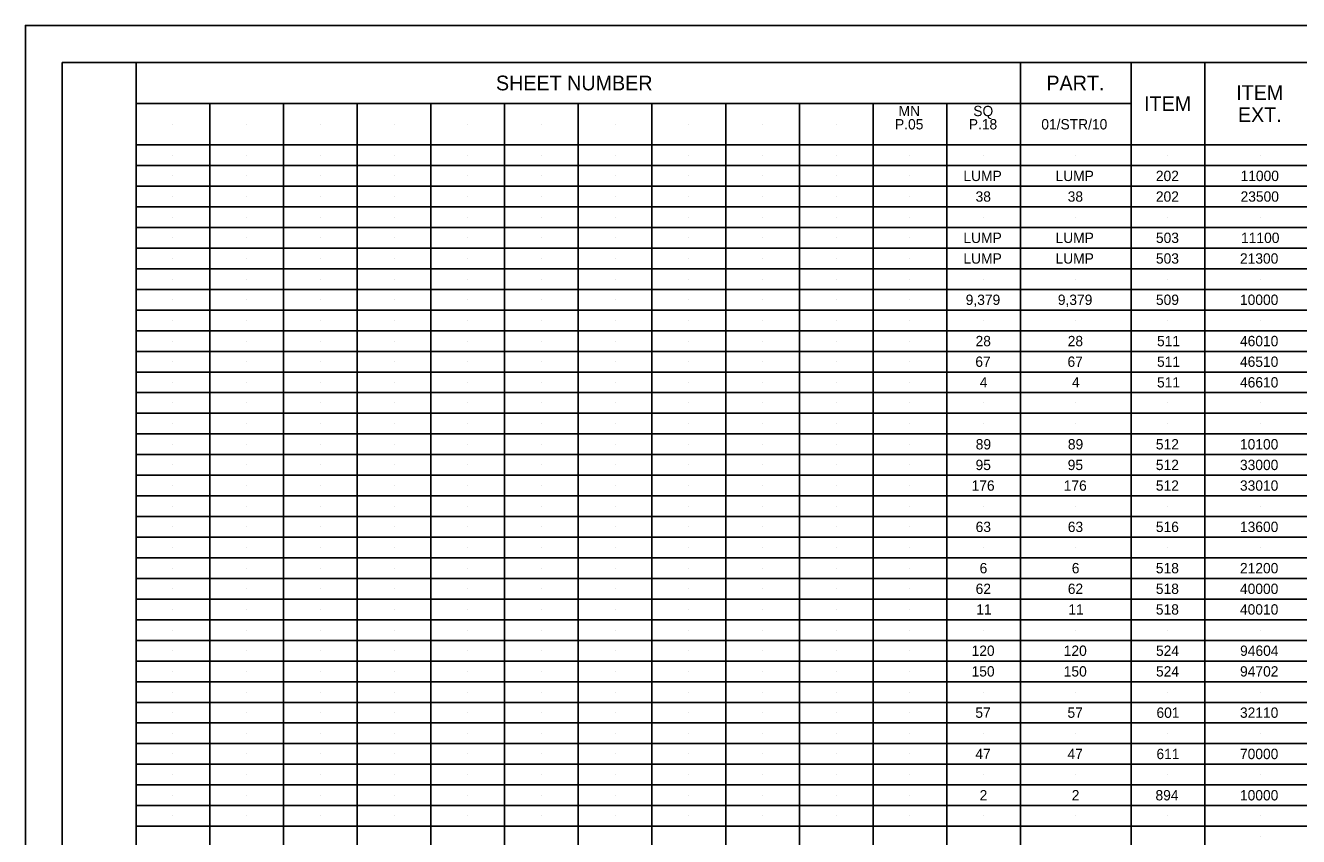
# Model space of a CAD drawing. Extents: x 0 to 34, y 0 to 22.
# Drawn here: x 0 to 17.27, y 11 to 22 of the extents above; entities that cross this region are included whole.
import ezdxf

# ---------------------------------------------------------------- set-up
doc = ezdxf.new("R2010")
doc.units = 0
for name, color, linetype in [('RD_P_Text', 7, 'Continuous'), ('SC_Scratch1', 7, 'Continuous'), ('SC_Scratch2', 7, 'Continuous'), ('SH_Border', 7, 'Continuous'), ('SH_Cut_Line', 7, 'Continuous'), ('SH_Data', 7, 'Continuous')]:
    doc.layers.add(name, color=color, linetype=linetype)

msp = doc.modelspace()

# ---------------------------------------------------------------- linework, layer by layer
at = {"layer": 'SC_Scratch1'}
for p, q in [((2, 20.66), (2, 20.66)), ((3, 20.66), (3, 20.66)), ((4, 20.66), (4, 20.66)), ((5, 20.66), (5, 20.66)), ((6, 20.66), (6, 20.66)), ((7, 20.66), (7, 20.66)), ((8, 20.66), (8, 20.66)), ((9, 20.66), (9, 20.66)), ((10, 20.66), (10, 20.66)), ((11, 20.66), (11, 20.66)), ((12, 20.66), (12, 20.66)), ((13, 20.66), (13, 20.66)), ((14.25, 20.66), (14.25, 20.66)), ((2, 20.24), (2, 20.24)), ((3, 20.24), (3, 20.24)), ((4, 20.24), (4, 20.24)), ((5, 20.24), (5, 20.24)), ((6, 20.24), (6, 20.24)), ((7, 20.24), (7, 20.24)), ((8, 20.24), (8, 20.24)), ((9, 20.24), (9, 20.24)), ((10, 20.24), (10, 20.24)), ((11, 20.24), (11, 20.24)), ((12, 20.24), (12, 20.24)), ((13, 20.24), (13, 20.24)), ((14.25, 20.24), (14.25, 20.24)), ((15.5, 20.24), (15.5, 20.24)), ((16.75, 20.24), (16.75, 20.24)), ((2, 19.96), (2, 19.96)), ((3, 19.96), (3, 19.96)), ((4, 19.96), (4, 19.96)), ((5, 19.96), (5, 19.96)), ((6, 19.96), (6, 19.96)), ((7, 19.96), (7, 19.96)), ((8, 19.96), (8, 19.96)), ((9, 19.96), (9, 19.96)), ((10, 19.96), (10, 19.96)), ((11, 19.96), (11, 19.96)), ((12, 19.96), (12, 19.96)), ((13, 19.96), (13, 19.96)), ((14.25, 19.96), (14.25, 19.96)), ((15.5, 19.96), (15.5, 19.96)), ((16.75, 19.96), (16.75, 19.96)), ((2, 19.68), (2, 19.68)), ((3, 19.68), (3, 19.68)), ((4, 19.68), (4, 19.68)), ((5, 19.68), (5, 19.68)), ((6, 19.68), (6, 19.68)), ((7, 19.68), (7, 19.68)), ((8, 19.68), (8, 19.68)), ((9, 19.68), (9, 19.68)), ((10, 19.68), (10, 19.68)), ((11, 19.68), (11, 19.68)), ((12, 19.68), (12, 19.68)), ((13, 19.68), (13, 19.68)), ((14.25, 19.68), (14.25, 19.68)), ((15.5, 19.68), (15.5, 19.68)), ((16.75, 19.68), (16.75, 19.68)), ((2, 19.4), (2, 19.4)), ((3, 19.4), (3, 19.4)), ((4, 19.4), (4, 19.4)), ((5, 19.4), (5, 19.4)), ((6, 19.4), (6, 19.4)), ((7, 19.4), (7, 19.4)), ((8, 19.4), (8, 19.4)), ((9, 19.4), (9, 19.4)), ((10, 19.4), (10, 19.4)), ((11, 19.4), (11, 19.4)), ((12, 19.4), (12, 19.4)), ((13, 19.4), (13, 19.4)), ((14.25, 19.4), (14.25, 19.4)), ((15.5, 19.4), (15.5, 19.4)), ((16.75, 19.4), (16.75, 19.4)), ((2, 19.12), (2, 19.12)), ((3, 19.12), (3, 19.12)), ((4, 19.12), (4, 19.12)), ((5, 19.12), (5, 19.12)), ((6, 19.12), (6, 19.12)), ((7, 19.12), (7, 19.12)), ((8, 19.12), (8, 19.12)), ((9, 19.12), (9, 19.12)), ((10, 19.12), (10, 19.12)), ((11, 19.12), (11, 19.12)), ((12, 19.12), (12, 19.12)), ((13, 19.12), (13, 19.12)), ((14.25, 19.12), (14.25, 19.12)), ((15.5, 19.12), (15.5, 19.12)), ((16.75, 19.12), (16.75, 19.12)), ((2, 18.84), (2, 18.84)), ((3, 18.84), (3, 18.84)), ((4, 18.84), (4, 18.84)), ((5, 18.84), (5, 18.84)), ((6, 18.84), (6, 18.84)), ((7, 18.84), (7, 18.84)), ((8, 18.84), (8, 18.84)), ((9, 18.84), (9, 18.84)), ((10, 18.84), (10, 18.84)), ((11, 18.84), (11, 18.84)), ((12, 18.84), (12, 18.84)), ((13, 18.84), (13, 18.84)), ((14.25, 18.84), (14.25, 18.84)), ((15.5, 18.84), (15.5, 18.84)), ((16.75, 18.84), (16.75, 18.84)), ((2, 18.56), (2, 18.56)), ((3, 18.56), (3, 18.56)), ((4, 18.56), (4, 18.56)), ((5, 18.56), (5, 18.56)), ((6, 18.56), (6, 18.56)), ((7, 18.56), (7, 18.56)), ((8, 18.56), (8, 18.56)), ((9, 18.56), (9, 18.56)), ((10, 18.56), (10, 18.56)), ((11, 18.56), (11, 18.56)), ((12, 18.56), (12, 18.56)), ((13, 18.56), (13, 18.56)), ((14.25, 18.56), (14.25, 18.56)), ((15.5, 18.56), (15.5, 18.56)), ((16.75, 18.56), (16.75, 18.56)), ((2, 18.28), (2, 18.28)), ((3, 18.28), (3, 18.28)), ((4, 18.28), (4, 18.28)), ((5, 18.28), (5, 18.28)), ((6, 18.28), (6, 18.28)), ((7, 18.28), (7, 18.28)), ((8, 18.28), (8, 18.28)), ((9, 18.28), (9, 18.28)), ((10, 18.28), (10, 18.28)), ((11, 18.28), (11, 18.28)), ((12, 18.28), (12, 18.28)), ((13, 18.28), (13, 18.28)), ((14.25, 18.28), (14.25, 18.28)), ((15.5, 18.28), (15.5, 18.28)), ((16.75, 18.28), (16.75, 18.28)), ((2, 18), (2, 18)), ((3, 18), (3, 18)), ((4, 18), (4, 18)), ((5, 18), (5, 18)), ((6, 18), (6, 18)), ((7, 18), (7, 18)), ((8, 18), (8, 18)), ((9, 18), (9, 18)), ((10, 18), (10, 18)), ((11, 18), (11, 18)), ((12, 18), (12, 18)), ((13, 18), (13, 18)), ((14.25, 18), (14.25, 18)), ((15.5, 18), (15.5, 18)), ((16.75, 18), (16.75, 18)), ((2, 17.72), (2, 17.72)), ((3, 17.72), (3, 17.72)), ((4, 17.72), (4, 17.72)), ((5, 17.72), (5, 17.72)), ((6, 17.72), (6, 17.72)), ((7, 17.72), (7, 17.72)), ((8, 17.72), (8, 17.72)), ((9, 17.72), (9, 17.72)), ((10, 17.72), (10, 17.72)), ((11, 17.72), (11, 17.72)), ((12, 17.72), (12, 17.72)), ((13, 17.72), (13, 17.72)), ((14.25, 17.72), (14.25, 17.72)), ((15.5, 17.72), (15.5, 17.72)), ((16.75, 17.72), (16.75, 17.72)), ((2, 17.44), (2, 17.44)), ((3, 17.44), (3, 17.44)), ((4, 17.44), (4, 17.44)), ((5, 17.44), (5, 17.44)), ((6, 17.44), (6, 17.44)), ((7, 17.44), (7, 17.44)), ((8, 17.44), (8, 17.44)), ((9, 17.44), (9, 17.44)), ((10, 17.44), (10, 17.44)), ((11, 17.44), (11, 17.44)), ((12, 17.44), (12, 17.44)), ((13, 17.44), (13, 17.44)), ((14.25, 17.44), (14.25, 17.44)), ((15.5, 17.44), (15.5, 17.44)), ((16.75, 17.44), (16.75, 17.44)), ((2, 17.16), (2, 17.16)), ((3, 17.16), (3, 17.16)), ((4, 17.16), (4, 17.16)), ((5, 17.16), (5, 17.16)), ((6, 17.16), (6, 17.16)), ((7, 17.16), (7, 17.16)), ((8, 17.16), (8, 17.16)), ((9, 17.16), (9, 17.16)), ((10, 17.16), (10, 17.16)), ((11, 17.16), (11, 17.16)), ((12, 17.16), (12, 17.16)), ((13, 17.16), (13, 17.16)), ((14.25, 17.16), (14.25, 17.16)), ((15.5, 17.16), (15.5, 17.16)), ((16.75, 17.16), (16.75, 17.16)), ((2, 16.88), (2, 16.88)), ((3, 16.88), (3, 16.88)), ((4, 16.88), (4, 16.88)), ((5, 16.88), (5, 16.88)), ((6, 16.88), (6, 16.88)), ((7, 16.88), (7, 16.88)), ((8, 16.88), (8, 16.88)), ((9, 16.88), (9, 16.88)), ((10, 16.88), (10, 16.88)), ((11, 16.88), (11, 16.88)), ((12, 16.88), (12, 16.88)), ((13, 16.88), (13, 16.88)), ((14.25, 16.88), (14.25, 16.88)), ((15.5, 16.88), (15.5, 16.88)), ((16.75, 16.88), (16.75, 16.88)), ((2, 16.6), (2, 16.6)), ((3, 16.6), (3, 16.6)), ((4, 16.6), (4, 16.6)), ((5, 16.6), (5, 16.6)), ((6, 16.6), (6, 16.6)), ((7, 16.6), (7, 16.6)), ((8, 16.6), (8, 16.6)), ((9, 16.6), (9, 16.6)), ((10, 16.6), (10, 16.6)), ((11, 16.6), (11, 16.6)), ((12, 16.6), (12, 16.6)), ((13, 16.6), (13, 16.6)), ((14.25, 16.6), (14.25, 16.6)), ((15.5, 16.6), (15.5, 16.6)), ((16.75, 16.6), (16.75, 16.6)), ((2, 16.32), (2, 16.32)), ((3, 16.32), (3, 16.32)), ((4, 16.32), (4, 16.32)), ((5, 16.32), (5, 16.32)), ((6, 16.32), (6, 16.32)), ((7, 16.32), (7, 16.32)), ((8, 16.32), (8, 16.32)), ((9, 16.32), (9, 16.32)), ((10, 16.32), (10, 16.32)), ((11, 16.32), (11, 16.32)), ((12, 16.32), (12, 16.32)), ((13, 16.32), (13, 16.32)), ((14.25, 16.32), (14.25, 16.32)), ((15.5, 16.32), (15.5, 16.32)), ((16.75, 16.32), (16.75, 16.32)), ((2, 16.04), (2, 16.04)), ((3, 16.04), (3, 16.04)), ((4, 16.04), (4, 16.04)), ((5, 16.04), (5, 16.04)), ((6, 16.04), (6, 16.04)), ((7, 16.04), (7, 16.04)), ((8, 16.04), (8, 16.04)), ((9, 16.04), (9, 16.04)), ((10, 16.04), (10, 16.04)), ((11, 16.04), (11, 16.04)), ((12, 16.04), (12, 16.04)), ((13, 16.04), (13, 16.04)), ((14.25, 16.04), (14.25, 16.04)), ((15.5, 16.04), (15.5, 16.04)), ((16.75, 16.04), (16.75, 16.04)), ((2, 15.76), (2, 15.76)), ((3, 15.76), (3, 15.76)), ((4, 15.76), (4, 15.76)), ((5, 15.76), (5, 15.76)), ((6, 15.76), (6, 15.76)), ((7, 15.76), (7, 15.76)), ((8, 15.76), (8, 15.76)), ((9, 15.76), (9, 15.76)), ((10, 15.76), (10, 15.76)), ((11, 15.76), (11, 15.76)), ((12, 15.76), (12, 15.76)), ((13, 15.76), (13, 15.76)), ((14.25, 15.76), (14.25, 15.76)), ((15.5, 15.76), (15.5, 15.76)), ((16.75, 15.76), (16.75, 15.76)), ((2, 15.48), (2, 15.48)), ((3, 15.48), (3, 15.48)), ((4, 15.48), (4, 15.48)), ((5, 15.48), (5, 15.48)), ((6, 15.48), (6, 15.48)), ((7, 15.48), (7, 15.48)), ((8, 15.48), (8, 15.48)), ((9, 15.48), (9, 15.48)), ((10, 15.48), (10, 15.48)), ((11, 15.48), (11, 15.48)), ((12, 15.48), (12, 15.48)), ((13, 15.48), (13, 15.48)), ((14.25, 15.48), (14.25, 15.48)), ((15.5, 15.48), (15.5, 15.48)), ((16.75, 15.48), (16.75, 15.48)), ((2, 15.2), (2, 15.2)), ((3, 15.2), (3, 15.2)), ((4, 15.2), (4, 15.2)), ((5, 15.2), (5, 15.2)), ((6, 15.2), (6, 15.2)), ((7, 15.2), (7, 15.2)), ((8, 15.2), (8, 15.2)), ((9, 15.2), (9, 15.2)), ((10, 15.2), (10, 15.2)), ((11, 15.2), (11, 15.2)), ((12, 15.2), (12, 15.2)), ((13, 15.2), (13, 15.2)), ((14.25, 15.2), (14.25, 15.2)), ((15.5, 15.2), (15.5, 15.2)), ((16.75, 15.2), (16.75, 15.2)), ((2, 14.92), (2, 14.92)), ((3, 14.92), (3, 14.92)), ((4, 14.92), (4, 14.92)), ((5, 14.92), (5, 14.92)), ((6, 14.92), (6, 14.92)), ((7, 14.92), (7, 14.92)), ((8, 14.92), (8, 14.92)), ((9, 14.92), (9, 14.92)), ((10, 14.92), (10, 14.92)), ((11, 14.92), (11, 14.92)), ((12, 14.92), (12, 14.92)), ((13, 14.92), (13, 14.92)), ((14.25, 14.92), (14.25, 14.92)), ((15.5, 14.92), (15.5, 14.92)), ((16.75, 14.92), (16.75, 14.92)), ((2, 14.64), (2, 14.64)), ((3, 14.64), (3, 14.64)), ((4, 14.64), (4, 14.64)), ((5, 14.64), (5, 14.64)), ((6, 14.64), (6, 14.64)), ((7, 14.64), (7, 14.64)), ((8, 14.64), (8, 14.64)), ((9, 14.64), (9, 14.64)), ((10, 14.64), (10, 14.64)), ((11, 14.64), (11, 14.64)), ((12, 14.64), (12, 14.64)), ((13, 14.64), (13, 14.64)), ((14.25, 14.64), (14.25, 14.64)), ((15.5, 14.64), (15.5, 14.64)), ((16.75, 14.64), (16.75, 14.64)), ((2, 14.36), (2, 14.36)), ((3, 14.36), (3, 14.36)), ((4, 14.36), (4, 14.36)), ((5, 14.36), (5, 14.36)), ((6, 14.36), (6, 14.36)), ((7, 14.36), (7, 14.36)), ((8, 14.36), (8, 14.36)), ((9, 14.36), (9, 14.36)), ((10, 14.36), (10, 14.36)), ((11, 14.36), (11, 14.36)), ((12, 14.36), (12, 14.36)), ((13, 14.36), (13, 14.36)), ((14.25, 14.36), (14.25, 14.36)), ((15.5, 14.36), (15.5, 14.36)), ((16.75, 14.36), (16.75, 14.36)), ((2, 14.08), (2, 14.08)), ((3, 14.08), (3, 14.08)), ((4, 14.08), (4, 14.08)), ((5, 14.08), (5, 14.08)), ((6, 14.08), (6, 14.08)), ((7, 14.08), (7, 14.08)), ((8, 14.08), (8, 14.08)), ((9, 14.08), (9, 14.08)), ((10, 14.08), (10, 14.08)), ((11, 14.08), (11, 14.08)), ((12, 14.08), (12, 14.08)), ((13, 14.08), (13, 14.08)), ((14.25, 14.08), (14.25, 14.08)), ((15.5, 14.08), (15.5, 14.08)), ((16.75, 14.08), (16.75, 14.08)), ((2, 13.8), (2, 13.8)), ((3, 13.8), (3, 13.8)), ((4, 13.8), (4, 13.8)), ((5, 13.8), (5, 13.8)), ((6, 13.8), (6, 13.8)), ((7, 13.8), (7, 13.8)), ((8, 13.8), (8, 13.8)), ((9, 13.8), (9, 13.8)), ((10, 13.8), (10, 13.8)), ((11, 13.8), (11, 13.8)), ((12, 13.8), (12, 13.8)), ((13, 13.8), (13, 13.8)), ((14.25, 13.8), (14.25, 13.8)), ((15.5, 13.8), (15.5, 13.8)), ((16.75, 13.8), (16.75, 13.8)), ((2, 13.52), (2, 13.52)), ((3, 13.52), (3, 13.52)), ((4, 13.52), (4, 13.52)), ((5, 13.52), (5, 13.52)), ((6, 13.52), (6, 13.52)), ((7, 13.52), (7, 13.52)), ((8, 13.52), (8, 13.52)), ((9, 13.52), (9, 13.52)), ((10, 13.52), (10, 13.52)), ((11, 13.52), (11, 13.52)), ((12, 13.52), (12, 13.52)), ((13, 13.52), (13, 13.52)), ((14.25, 13.52), (14.25, 13.52)), ((15.5, 13.52), (15.5, 13.52)), ((16.75, 13.52), (16.75, 13.52)), ((2, 13.24), (2, 13.24)), ((3, 13.24), (3, 13.24)), ((4, 13.24), (4, 13.24)), ((5, 13.24), (5, 13.24)), ((6, 13.24), (6, 13.24)), ((7, 13.24), (7, 13.24)), ((8, 13.24), (8, 13.24)), ((9, 13.24), (9, 13.24)), ((10, 13.24), (10, 13.24)), ((11, 13.24), (11, 13.24)), ((12, 13.24), (12, 13.24)), ((13, 13.24), (13, 13.24)), ((14.25, 13.24), (14.25, 13.24)), ((15.5, 13.24), (15.5, 13.24)), ((16.75, 13.24), (16.75, 13.24)), ((2, 12.96), (2, 12.96)), ((3, 12.96), (3, 12.96)), ((4, 12.96), (4, 12.96)), ((5, 12.96), (5, 12.96)), ((6, 12.96), (6, 12.96)), ((7, 12.96), (7, 12.96)), ((8, 12.96), (8, 12.96)), ((9, 12.96), (9, 12.96)), ((10, 12.96), (10, 12.96)), ((11, 12.96), (11, 12.96)), ((12, 12.96), (12, 12.96)), ((13, 12.96), (13, 12.96)), ((14.25, 12.96), (14.25, 12.96)), ((15.5, 12.96), (15.5, 12.96)), ((16.75, 12.96), (16.75, 12.96)), ((2, 12.68), (2, 12.68)), ((3, 12.68), (3, 12.68)), ((4, 12.68), (4, 12.68)), ((5, 12.68), (5, 12.68)), ((6, 12.68), (6, 12.68)), ((7, 12.68), (7, 12.68)), ((8, 12.68), (8, 12.68)), ((9, 12.68), (9, 12.68)), ((10, 12.68), (10, 12.68)), ((11, 12.68), (11, 12.68)), ((12, 12.68), (12, 12.68)), ((13, 12.68), (13, 12.68)), ((14.25, 12.68), (14.25, 12.68)), ((15.5, 12.68), (15.5, 12.68)), ((16.75, 12.68), (16.75, 12.68)), ((2, 12.4), (2, 12.4)), ((3, 12.4), (3, 12.4)), ((4, 12.4), (4, 12.4)), ((5, 12.4), (5, 12.4)), ((6, 12.4), (6, 12.4)), ((7, 12.4), (7, 12.4)), ((8, 12.4), (8, 12.4)), ((9, 12.4), (9, 12.4)), ((10, 12.4), (10, 12.4)), ((11, 12.4), (11, 12.4)), ((12, 12.4), (12, 12.4)), ((13, 12.4), (13, 12.4)), ((14.25, 12.4), (14.25, 12.4)), ((15.5, 12.4), (15.5, 12.4)), ((16.75, 12.4), (16.75, 12.4)), ((2, 12.12), (2, 12.12)), ((3, 12.12), (3, 12.12)), ((4, 12.12), (4, 12.12)), ((5, 12.12), (5, 12.12)), ((6, 12.12), (6, 12.12)), ((7, 12.12), (7, 12.12)), ((8, 12.12), (8, 12.12)), ((9, 12.12), (9, 12.12)), ((10, 12.12), (10, 12.12)), ((11, 12.12), (11, 12.12)), ((12, 12.12), (12, 12.12)), ((13, 12.12), (13, 12.12)), ((14.25, 12.12), (14.25, 12.12)), ((15.5, 12.12), (15.5, 12.12)), ((16.75, 12.12), (16.75, 12.12)), ((2, 11.84), (2, 11.84)), ((3, 11.84), (3, 11.84)), ((4, 11.84), (4, 11.84)), ((5, 11.84), (5, 11.84)), ((6, 11.84), (6, 11.84)), ((7, 11.84), (7, 11.84)), ((8, 11.84), (8, 11.84)), ((9, 11.84), (9, 11.84)), ((10, 11.84), (10, 11.84)), ((11, 11.84), (11, 11.84)), ((12, 11.84), (12, 11.84)), ((13, 11.84), (13, 11.84)), ((14.25, 11.84), (14.25, 11.84)), ((15.5, 11.84), (15.5, 11.84)), ((16.75, 11.84), (16.75, 11.84)), ((2, 11.56), (2, 11.56)), ((3, 11.56), (3, 11.56)), ((4, 11.56), (4, 11.56)), ((5, 11.56), (5, 11.56)), ((6, 11.56), (6, 11.56)), ((7, 11.56), (7, 11.56)), ((8, 11.56), (8, 11.56)), ((9, 11.56), (9, 11.56)), ((10, 11.56), (10, 11.56)), ((11, 11.56), (11, 11.56)), ((12, 11.56), (12, 11.56)), ((13, 11.56), (13, 11.56)), ((14.25, 11.56), (14.25, 11.56)), ((15.5, 11.56), (15.5, 11.56)), ((16.75, 11.56), (16.75, 11.56)), ((2, 11.28), (2, 11.28)), ((3, 11.28), (3, 11.28)), ((4, 11.28), (4, 11.28)), ((5, 11.28), (5, 11.28)), ((6, 11.28), (6, 11.28)), ((7, 11.28), (7, 11.28)), ((8, 11.28), (8, 11.28)), ((9, 11.28), (9, 11.28)), ((10, 11.28), (10, 11.28)), ((11, 11.28), (11, 11.28)), ((12, 11.28), (12, 11.28)), ((13, 11.28), (13, 11.28)), ((14.25, 11.28), (14.25, 11.28)), ((15.5, 11.28), (15.5, 11.28)), ((16.75, 11.28), (16.75, 11.28)), ((16.75, 11), (16.75, 11))]:
    msp.add_line(p, q, dxfattribs=at)
at = {"layer": 'SH_Border'}
for points in [[(0.5, 21.5), (1.5, 21.5), (1.5, 0.5), (0.5, 0.5)], [(1.5, 21.5), (33.5, 21.5), (33.5, 0.5), (1.5, 0.5)]]:
    msp.add_lwpolyline(points, close=True, dxfattribs=at)
at = {"layer": 'SH_Cut_Line'}
msp.add_lwpolyline([(0, 0), (34, 0), (34, 22), (0, 22)], close=True, dxfattribs=at)
at = {"layer": 'SH_Data'}
for p, q in [((13.5, 21.5), (13.5, 0.5)), ((15, 21.5), (15, 0.5)), ((16, 21.5), (16, 0.5)), ((15, 20.94), (1.5, 20.94)), ((2.5, 20.94), (2.5, 0.5)), ((3.5, 20.94), (3.5, 0.5)), ((4.5, 20.94), (4.5, 0.5)), ((5.5, 20.94), (5.5, 0.5)), ((6.5, 20.94), (6.5, 0.5)), ((7.5, 20.94), (7.5, 0.5)), ((8.5, 20.94), (8.5, 0.5)), ((9.5, 20.94), (9.5, 0.5)), ((10.5, 20.94), (10.5, 0.5)), ((11.5, 20.94), (11.5, 0.5)), ((12.5, 20.94), (12.5, 0.5)), ((32, 20.38), (1.5, 20.38)), ((32, 20.1), (1.5, 20.1)), ((32, 19.82), (1.5, 19.82)), ((32, 19.54), (1.5, 19.54)), ((32, 19.26), (1.5, 19.26)), ((32, 18.98), (1.5, 18.98)), ((32, 18.7), (1.5, 18.7)), ((32, 18.42), (1.5, 18.42)), ((32, 18.14), (1.5, 18.14)), ((32, 17.86), (1.5, 17.86)), ((32, 17.58), (1.5, 17.58)), ((32, 17.3), (1.5, 17.3)), ((32, 17.02), (1.5, 17.02)), ((32, 16.74), (1.5, 16.74)), ((32, 16.46), (1.5, 16.46)), ((32, 16.18), (1.5, 16.18)), ((32, 15.9), (1.5, 15.9)), ((32, 15.62), (1.5, 15.62)), ((32, 15.34), (1.5, 15.34)), ((32, 15.06), (1.5, 15.06)), ((32, 14.78), (1.5, 14.78)), ((32, 14.5), (1.5, 14.5)), ((32, 14.22), (1.5, 14.22)), ((32, 13.94), (1.5, 13.94)), ((32, 13.66), (1.5, 13.66)), ((32, 13.38), (1.5, 13.38)), ((32, 13.1), (1.5, 13.1)), ((32, 12.82), (1.5, 12.82)), ((32, 12.54), (1.5, 12.54)), ((32, 12.26), (1.5, 12.26)), ((32, 11.98), (1.5, 11.98)), ((32, 11.7), (1.5, 11.7)), ((32, 11.42), (1.5, 11.42)), ((32, 11.14), (1.5, 11.14))]:
    msp.add_line(p, q, dxfattribs=at)

# ---------------------------------------------------------------- texts
at = {"layer": 'RD_P_Text'}
for s, p in [('P.05', (11.797, 20.59)), ('P.18', (12.798, 20.59)), ('01/STR/10', (13.782, 20.59)), ('LUMP', (12.725, 19.89)), ('LUMP', (13.975, 19.89)), ('202', (15.336, 19.89)), ('11000', (16.485, 19.89)), ('38', (12.89, 19.61)), ('38', (14.14, 19.61)), ('202', (15.336, 19.61)), ('23500', (16.485, 19.61)), ('LUMP', (12.725, 19.05)), ('LUMP', (13.975, 19.05)), ('503', (15.337, 19.05)), ('11100', (16.492, 19.05)), ('LUMP', (12.725, 18.77)), ('LUMP', (13.975, 18.77)), ('503', (15.337, 18.77)), ('21300', (16.477, 18.77)), ('9,379', (12.756, 18.21)), ('9,379', (14.006, 18.21)), ('509', (15.337, 18.21)), ('10000', (16.477, 18.21)), ('28', (12.89, 17.65)), ('28', (14.14, 17.65)), ('511', (15.352, 17.65)), ('46010', (16.477, 17.65)), ('67', (12.887, 17.37)), ('67', (14.137, 17.37)), ('511', (15.352, 17.37)), ('46510', (16.477, 17.37)), ('4', (12.947, 17.09)), ('4', (14.197, 17.09)), ('511', (15.352, 17.09)), ('46610', (16.477, 17.09)), ('89', (12.892, 16.25)), ('89', (14.142, 16.25)), ('512', (15.336, 16.25)), ('10100', (16.477, 16.25)), ('95', (12.89, 15.97)), ('95', (14.14, 15.97)), ('512', (15.336, 15.97)), ('33000', (16.477, 15.97)), ('176', (12.836, 15.69)), ('176', (14.086, 15.69)), ('512', (15.336, 15.69)), ('33010', (16.477, 15.69)), ('63', (12.891, 15.13)), ('63', (14.141, 15.13)), ('516', (15.336, 15.13)), ('13600', (16.477, 15.13)), ('6', (12.945, 14.57)), ('6', (14.195, 14.57)), ('518', (15.336, 14.57)), ('21200', (16.477, 14.57)), ('62', (12.891, 14.29)), ('62', (14.141, 14.29)), ('518', (15.336, 14.29)), ('40000', (16.477, 14.29)), ('11', (12.899, 14.01)), ('11', (14.149, 14.01)), ('518', (15.336, 14.01)), ('40010', (16.477, 14.01)), ('120', (12.836, 13.45)), ('120', (14.086, 13.45)), ('524', (15.338, 13.45)), ('94604', (16.479, 13.45)), ('150', (12.836, 13.17)), ('150', (14.086, 13.17)), ('524', (15.338, 13.17)), ('94702', (16.478, 13.17)), ('57', (12.887, 12.61)), ('57', (14.137, 12.61)), ('601', (15.344, 12.61)), ('32110', (16.477, 12.61)), ('47', (12.887, 12.05)), ('47', (14.137, 12.05)), ('611', (15.344, 12.05)), ('70000', (16.477, 12.05)), ('2', (12.945, 11.49)), ('2', (14.195, 11.49)), ('894', (15.331, 11.49)), ('10000', (16.477, 11.49))]:
    msp.add_text(s, height=0.14, dxfattribs=at).set_placement(p)
at = {"layer": 'SC_Scratch2'}
for s, p in [('MN', (11.845, 20.77)), ('SQ', (12.859, 20.77))]:
    msp.add_text(s, height=0.14, dxfattribs=at).set_placement(p)
at = {"layer": 'SH_Data'}
for s, p in [('SHEET NUMBER', (6.383, 21.12)), ('PART.', (13.851, 21.12)), ('ITEM', (16.426, 20.99)), ('ITEM', (15.176, 20.84)), ('EXT.', (16.449, 20.69))]:
    msp.add_text(s, height=0.2, dxfattribs=at).set_placement(p)

doc.saveas('drawing.dxf')
